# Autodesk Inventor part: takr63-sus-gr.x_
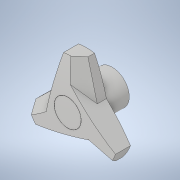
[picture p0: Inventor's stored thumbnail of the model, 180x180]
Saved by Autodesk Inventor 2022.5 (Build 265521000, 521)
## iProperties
Created: 2021-08
Part Number: takr63-sus-gr.x_
Material: 一般
Document SubType Name: Modeling
Designer: ImaoCorp
Density: 1 g/cm^3
Appearance: 既定
Sending System: SOLIDWORKS 2019-2019304
MC: AMD64
MC_MODEL: Intel64 Family 6 Model 60 Stepping 3, GenuineIntel
OS: Windows_NT
FRU: Parasolid Version 31.0, build 290,  9- 1-2019
FORMAT: text
GUISE: transmit
KEY: takr63-sus-gr
FILE: takr63-sus-gr.x_t
DATE: Wed Aug 11 15:01:59 2021
Author: ImaoCorp
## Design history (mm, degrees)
feature "Base1"
node "ソリッド1"
